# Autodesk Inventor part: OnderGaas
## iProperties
Created: 2010-03
Part Number: OnderGaas
Document SubType Name: Modeling
Designer: Ferry
Density: 1 g/cm^3
Author: Ferry
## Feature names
1. Extrusion1
